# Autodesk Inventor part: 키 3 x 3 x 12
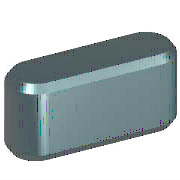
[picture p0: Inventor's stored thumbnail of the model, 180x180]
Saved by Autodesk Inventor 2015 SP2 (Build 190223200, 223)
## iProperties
Created: 2012-02
Part Number: 키 3 x 3 x 12
Material: 강철, 연강
Description: 키 및 해당 키홈
Document SubType Name: Modeling
Standard: KS B 1311
Designer: mduedu
Standards Organization: KS
Language: ko-KR
Size Designation: 3 x 3 x 12
Categories: <MemberInstance><Categories><Category DisplayName="샤프트 부품" InternalName="7f7aeb1f-a693-4053-b835-cee3144e0d98" Mnemonic="SHFT"><Category DisplayName="키" Interna
Density: 1 g/cm^3
Appearance: 강철
IsCustomPart: 1
Author: mduedu
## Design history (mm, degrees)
workplane "Work Plane1"
workplane "Work Plane2"
sketch "스케치1"
  geometry: L1 (1.5, 1.5)-(10.5, 1.5); L2 (10.5, -1.5)-(1.5, -1.5); L3 (0, 9.4)-(0, -7.4) reference; L4 (-5, 0)-(30, 0) reference; L5 (12, 0)-(12, 7); A1 r 1.5 centre (1.5, 0) between (1.5, 1.5) and (1.5, -1.5); A2 r 1.5 centre (10.5, 0) between (10.5, -1.5) and (10.5, 1.5)
  constraints: 6 end point, 5 point on circle, 4 tangent, 3 point on line, 2 centre point, 1 horizontal, 1 parallel, 1 perpendicular
  dimensions: "d0" = 1.5 radius of A1 (= 0.5 x PB); "d13" = 1.5 radius of A2 (= 0.5 x PB); "d14" = 12 distance between parallel lines of L5 L3 (= NLG)
extrude "본체1" new body sketch "스케치1" taper "d3" = 0 deg; stored distance "d4" = 10
workplane "Work Plane3"
body "Solid1"
chamfer "모따기1" distance "d8" = 0.25 (= PHH); stored, may be unused: second distance "d9" = 0.25 (= PHH), angle "d15" = 45 deg
other parameters: "d1" = -1.8 (= -PNT), "d2" = 1.2 (= PH - PNT), "NLG" = 12 [user parameter; used in 3 equation terms], "PB" = 3 [user parameter; used in 2 equation terms], "PNT" = 1.8 [user parameter; used in 2 equation terms], "PH" = 3 [user parameter; used in 1 equation term], "PHH" = 0.25 [user parameter; used in 2 equation terms], "d10" = 0, "d16" = 0, "d17" = 0, "d18" = 0, "WDMIN" = 8 [user parameter], "PLB2" = 12 (= NLG) [user parameter], "PLB1" = 12 (= NLG) [user parameter], "RR" = 0.08 [user parameter], "PUEB" = 1.4 [user parameter]
